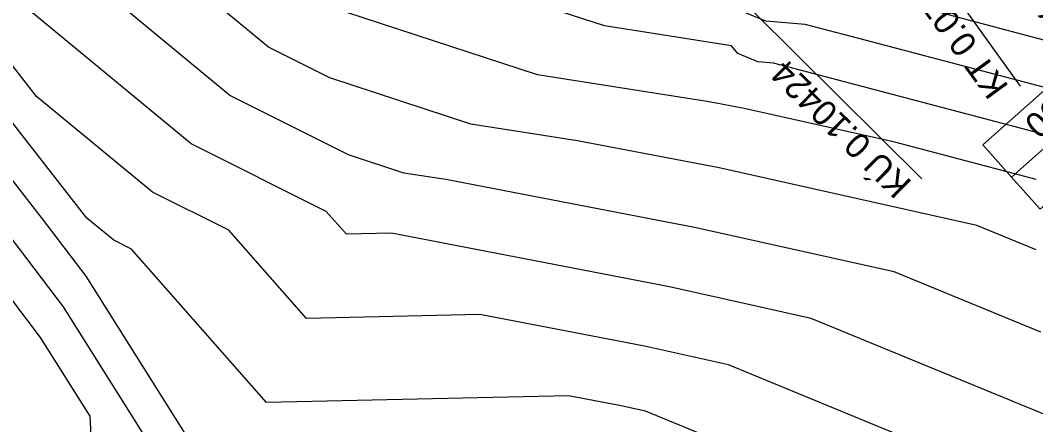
# Model space of a CAD drawing. Extents: x -549394 to -546608, y -1037055 to -1033629.
# Drawn here: x -547957.5 to -547816, y -1035700.8 to -1035644.5 of the extents above; entities that cross this region are included whole.
import ezdxf

# ---------------------------------------------------------------- set-up
doc = ezdxf.new("R2010")
doc.units = 0
for name, color, linetype in [('hlavni_vrst', 7, 'Continuous'), ('norm_vrst', 7, 'Continuous'), ('x_popis_oblouky_C111', 7, 'Continuous')]:
    doc.layers.add(name, color=color, linetype=linetype)

msp = doc.modelspace()

# ---------------------------------------------------------------- linework, layer by layer
at = {"layer": 'hlavni_vrst'}
for p, q in [((-547876.12, -1035645.25), (-547895, -1035639.08)), ((-547955.26, -1035655.06), (-547962.68, -1035645.56)), ((-547858.39, -1035648.03), (-547876.12, -1035645.25)), ((-547857.52, -1035649.11), (-547858.39, -1035648.03)), ((-547854.74, -1035650.24), (-547857.52, -1035649.11)), ((-547852.54, -1035650.43), (-547854.74, -1035650.24)), ((-547849.55, -1035651.2), (-547852.54, -1035650.43)), ((-547814.63, -1035660.41), (-547849.55, -1035651.2)), ((-547939.12, -1035668.38), (-547955.26, -1035655.06)), ((-547928.46, -1035673.71), (-547939.12, -1035668.38)), ((-547917.65, -1035685.98), (-547928.46, -1035673.71)), ((-547893.46, -1035685.43), (-547917.65, -1035685.98)), ((-547870.53, -1035689.84), (-547893.46, -1035685.43)), ((-547858.83, -1035692.44), (-547870.53, -1035689.84)), ((-547821.55, -1035707.76), (-547858.83, -1035692.44))]:
    msp.add_line(p, q, dxfattribs=at)
at = {"layer": 'norm_vrst'}
for p, q in [((-547922.94, -1035648.21), (-547930.82, -1035641.7)), ((-547885.43, -1035652.08), (-547916.99, -1035641.76)), ((-547853.61, -1035644.58), (-547860.56, -1035641.77)), ((-547933.73, -1035661.65), (-547956.34, -1035642.99)), ((-547928.33, -1035654.93), (-547943.58, -1035642.34)), ((-547812.01, -1035647.98), (-547831.81, -1035642.75)), ((-547848.14, -1035645.06), (-547853.61, -1035644.58)), ((-547840.68, -1035646.98), (-547848.14, -1035645.06)), ((-547813.32, -1035654.2), (-547840.68, -1035646.98)), ((-547948.24, -1035672.03), (-547966.27, -1035648.96)), ((-547914.4, -1035652.48), (-547922.94, -1035648.21)), ((-547861.54, -1035655.82), (-547885.43, -1035652.08)), ((-547954.42, -1035672.11), (-547969.87, -1035652.36)), ((-547894.75, -1035658.91), (-547914.4, -1035652.48)), ((-547911.8, -1035663.2), (-547928.33, -1035654.93)), ((-547856.64, -1035656.76), (-547861.54, -1035655.82)), ((-547835.62, -1035661.44), (-547856.64, -1035656.76)), ((-547879.87, -1035661.23), (-547894.75, -1035658.91)), ((-547914.88, -1035671.09), (-547933.73, -1035661.65)), ((-547860.11, -1035665.03), (-547879.87, -1035661.23)), ((-547815.94, -1035666.63), (-547835.62, -1035661.44)), ((-547954.71, -1035688.66), (-547974.52, -1035662.54)), ((-547904.07, -1035665.73), (-547911.8, -1035663.2)), ((-547951.53, -1035684.39), (-547966.27, -1035664.95)), ((-547898.2, -1035666.65), (-547904.07, -1035665.73)), ((-547824.21, -1035673.02), (-547860.11, -1035665.03)), ((-547863.58, -1035673.3), (-547898.2, -1035666.65)), ((-547912.07, -1035674.27), (-547914.88, -1035671.09)), ((-547948.36, -1035680.11), (-547954.42, -1035672.11)), ((-547944.51, -1035675.1), (-547948.24, -1035672.03)), ((-547835.75, -1035679.5), (-547863.58, -1035673.3)), ((-547815.92, -1035676.43), (-547824.21, -1035673.02)), ((-547905.8, -1035674.13), (-547912.07, -1035674.27)), ((-547867.05, -1035681.57), (-547905.8, -1035674.13)), ((-547942.05, -1035676.33), (-547944.51, -1035675.1)), ((-547923.23, -1035697.69), (-547942.05, -1035676.33)), ((-547932.56, -1035705.15), (-547948.36, -1035680.11)), ((-547815.27, -1035687.91), (-547835.75, -1035679.5)), ((-547847.29, -1035685.97), (-547867.05, -1035681.57)), ((-547937.99, -1035705.85), (-547951.53, -1035684.39)), ((-547814.62, -1035699.39), (-547847.29, -1035685.97)), ((-547947.81, -1035699.61), (-547954.71, -1035688.66)), ((-547881.11, -1035696.74), (-547923.23, -1035697.69)), ((-547874, -1035698.11), (-547881.11, -1035696.74)), ((-547870.37, -1035698.92), (-547874, -1035698.11)), ((-547947.29, -1035708.7), (-547947.81, -1035699.61)), ((-547858.8, -1035703.67), (-547870.37, -1035698.92))]:
    msp.add_line(p, q, dxfattribs=at)
at = {"layer": 'x_popis_oblouky_C111'}
for points in [[(-547841.94, -1035620.56), (-547818.19, -1035653.63)], [(-547861.23, -1035637.4), (-547831.86, -1035666.54)]]:
    msp.add_lwpolyline(points, dxfattribs=at)
for points in [[(-547796.93, -1035646.39), (-547819.38, -1035666.29), (-547823.36, -1035661.8), (-547800.91, -1035641.9)], [(-547792.95, -1035650.88), (-547815.4, -1035670.78), (-547819.38, -1035666.29), (-547796.93, -1035646.39)]]:
    msp.add_lwpolyline(points, close=True, dxfattribs=at)

# ---------------------------------------------------------------- texts
for s, rotation, p in [('TK 0.07474', 140.3303, (-547809.16, -1035644.8)), ('KT 0.07849', 126.1294, (-547819.68, -1035653.69)), ('t=1.890', 221.5842, (-547806.06, -1035648.08)), ('KÚ 0.10424', 135.5577, (-547833.12, -1035667.03))]:
    msp.add_text(s, height=3.5, rotation=rotation, dxfattribs=at).set_placement(p)

doc.saveas('drawing.dxf')
